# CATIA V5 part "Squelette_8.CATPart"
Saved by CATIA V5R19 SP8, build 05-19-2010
Part number: Squelette_8
Publications: "Spline.1", "Plan.1", "Esquisse.1", "Diamètre bielle"
Bounding box of the stored display mesh (mm): x -270 to 135.666, y -4.859 to 573.118, z -190.413 to 44.032
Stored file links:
  J:\CFAO_IFMA\Squelette_8.CATPart
  J:\CFAO_IFMA\Squelette.CATProduct
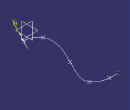
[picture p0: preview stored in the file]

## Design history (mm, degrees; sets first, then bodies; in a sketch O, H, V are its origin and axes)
Parameters
  `Diamètre bielle` = 20 mm
Set1
  Point1 "C": linked copy from another document
  Point2 "D": linked copy from another document
Set2
  Point3: (-120, 60, 0), relative to Point1
  Point4: (-100, 150, -170), relative to Point3
  Point5: (80, 0, 0), relative to Point2
  Point6: (120, -60, 0), relative to Point5
  Curve1: Elements (Point1; Point3; Point4; Point6; Point5; Point2)
  Plane1: type Normal, Curve Curve1, RefPoint Point1
  Sketch1 on Plane1, origin (61.2358, -4.8586, -0.7236), H (-0.4492, -0.8928, 0.0346), V (0.3521, -0.1413, 0.9252)
    circle A1 centre (-123.4386, 37.8242) radius 10
    point P1 (-123.4386, 37.8242)
    reference projected point E1 (-123.4386, 37.8242) from Point1
    radius A1 = 10 {= `Diamètre bielle` /2}
    coincidence: P1 E1
Body1 (main body)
